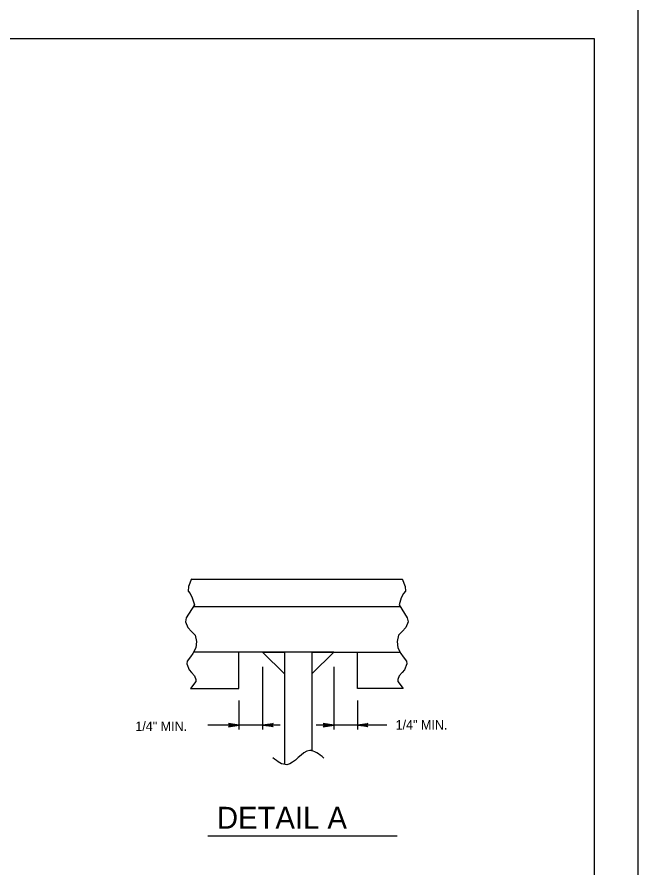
# Model space of a CAD drawing. Extents: x 638466 to 639375, y 297808 to 298996.
# Drawn here: x 639092.2 to 639307, y 298100.7 to 298395 of the extents above; entities that cross this region are included whole.
import ezdxf

# ---------------------------------------------------------------- set-up
doc = ezdxf.new("R2010")
doc.units = 0
for name, color, linetype in [('1', 7, 'Continuous'), ('2', 7, 'Continuous'), ('4', 7, 'Continuous'), ('PLT-BNDY', 7, 'Continuous')]:
    doc.layers.add(name, color=color, linetype=linetype)

msp = doc.modelspace()

# ---------------------------------------------------------------- linework, layer by layer
at = {"layer": '1'}
for p, q in [((639291.96, 298387.46), (638505.96, 298387.46)), ((639291.96, 297823.46), (639291.96, 298387.46))]:
    msp.add_line(p, q, dxfattribs=at)
for points in [[(639165.55, 298149.73), (639165.67, 298149.98), (639168.98, 298150.16), (639165.55, 298149.73), (639165.37, 298149.58), (639168.98, 298150.16), (639165.68, 298150.33), (639165.56, 298150.57), (639168.98, 298150.16), (639165.37, 298150.73), (639165.56, 298150.57)], [(639180.61, 298149.73), (639180.48, 298149.98), (639177.17, 298150.16), (639180.61, 298149.73), (639180.78, 298149.58), (639177.17, 298150.16), (639180.47, 298150.33), (639180.59, 298150.57), (639177.17, 298150.16), (639180.78, 298150.73), (639180.59, 298150.57)], [(639198.31, 298149.73), (639198.43, 298149.98), (639201.74, 298150.16), (639198.31, 298149.73), (639198.13, 298149.58), (639201.74, 298150.16), (639198.44, 298150.33), (639198.32, 298150.57), (639201.74, 298150.16), (639198.13, 298150.73), (639198.32, 298150.57)], [(639213.37, 298149.73), (639213.24, 298149.98), (639209.93, 298150.16), (639213.37, 298149.73), (639213.54, 298149.58), (639209.93, 298150.16), (639213.23, 298150.33), (639213.35, 298150.57), (639209.93, 298150.16), (639213.54, 298150.73), (639213.35, 298150.57)]]:
    msp.add_lwpolyline(points, dxfattribs=at)
at = {"layer": '2'}
for p, q in [((639152.58, 298200.63), (639225.41, 298200.63)), ((639153.26, 298191.15), (639224.73, 298191.15)), ((639194.19, 298175.4), (639153.3, 298175.4)), ((639168.98, 298162.83), (639168.98, 298175.4)), ((639184.73, 298175.4), (639184.73, 298136.65)), ((639194.18, 298175.4), (639224.75, 298175.4)), ((639194.18, 298175.4), (639194.18, 298141.16)), ((639209.93, 298162.83), (639209.93, 298175.4)), ((639152.19, 298162.83), (639168.98, 298162.83)), ((639225.8, 298162.83), (639209.93, 298162.83))]:
    msp.add_line(p, q, dxfattribs=at)
for points in [[(639152.6, 298200.67), (639151.57, 298198.09), (639151.44, 298196.4), (639152.08, 298195.63), (639152.86, 298194.2), (639153.63, 298191.75), (639150.79, 298187.22), (639150.53, 298185.8), (639151.31, 298183.86), (639152.6, 298182.56), (639153.89, 298181.27), (639154.28, 298179.07), (639154.02, 298176.87), (639152.99, 298174.93), (639152.21, 298173.77), (639151.05, 298172.21), (639150.92, 298171.31), (639151.82, 298169.24), (639152.6, 298168.33), (639153.63, 298167.17), (639154.02, 298165.87), (639154.02, 298165.23), (639152.19, 298162.83)], [(639225.39, 298200.67), (639226.43, 298198.09), (639226.56, 298196.4), (639225.91, 298195.63), (639225.13, 298194.2), (639224.36, 298191.75), (639227.2, 298187.22), (639227.46, 298185.8), (639226.68, 298183.86), (639225.39, 298182.56), (639224.1, 298181.27), (639223.71, 298179.07), (639223.97, 298176.87), (639225, 298174.93), (639225.78, 298173.77), (639226.94, 298172.21), (639227.07, 298171.31), (639226.17, 298169.24), (639225.39, 298168.33), (639224.36, 298167.17), (639223.97, 298165.87), (639223.97, 298165.23), (639225.8, 298162.83)]]:
    msp.add_lwpolyline(points, dxfattribs=at)
for points in [[(639184.73, 298175.4), (639184.73, 298167.84), (639177.17, 298175.4)], [(639194.18, 298175.4), (639194.18, 298167.84), (639201.74, 298175.4)]]:
    msp.add_lwpolyline(points, close=True, dxfattribs=at)
msp.add_spline([(639198.36, 298138.74), (639193.46, 298141.35), (639185.53, 298136.46), (639180.7, 298138.8)], degree=3, dxfattribs=at)
at = {"layer": '4'}
for p, q in [((639177.17, 298170.3), (639177.17, 298148.67)), ((639201.74, 298170.3), (639201.74, 298148.67)), ((639168.98, 298158.66), (639168.98, 298148.67)), ((639209.93, 298158.66), (639209.93, 298148.67)), ((639183.29, 298150.16), (639158.18, 298150.16)), ((639220.16, 298150.16), (639195.64, 298150.16)), ((639223.7, 298111.79), (639158.26, 298111.79))]:
    msp.add_line(p, q, dxfattribs=at)
at = {"layer": 'PLT-BNDY'}
msp.add_lwpolyline([(638465.96, 298402.46), (639306.96, 298402.46), (639306.96, 297808.46), (638465.96, 297808.46)], close=True, dxfattribs=at)

# ---------------------------------------------------------------- texts
at = {"layer": '4'}
for s, height, p in [('1/4" MIN.', 3.24, (639133.16, 298148.14)), ('1/4" MIN.', 3.24, (639223.15, 298148.62)), ('DETAIL A', 7.56, (639161.38, 298114.34))]:
    msp.add_text(s, height=height, dxfattribs=at).set_placement(p)

doc.saveas('drawing.dxf')
